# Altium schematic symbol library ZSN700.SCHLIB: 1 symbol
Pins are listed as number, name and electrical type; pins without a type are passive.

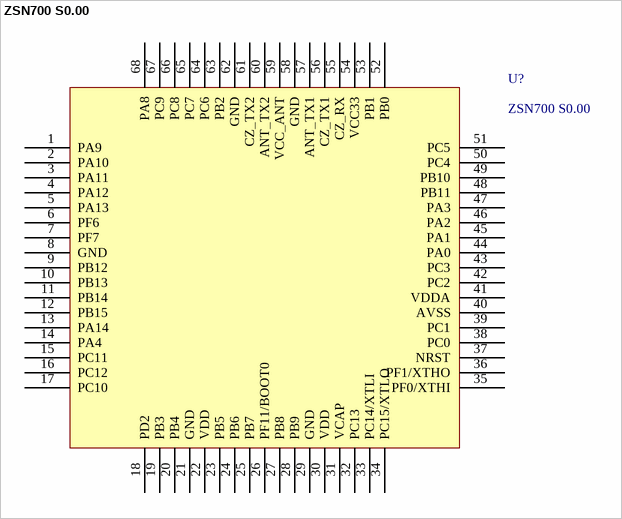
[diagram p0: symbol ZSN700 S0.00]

## ZSN700 S0.00
designator U?
物料代码: 78.59.00018; 名称: 集成电路; 厂商: ZHIYUAN; 贴片和直插: SMT; PCB备注: 200310hcj; 器件优选方案: 待导入物料
footprint ZSN700 S0.00
pins: 1 PA9, 2 PA10, 3 PA11, 4 PA12, 5 PA13, 6 PF6, 7 PF7, 8 GND, 9 PB12, 10 PB13, 11 PB14, 12 PB15, 13 PA14, 14 PA4, 15 PC11, 16 PC12, 17 PC10, 18 PD2, 19 PB3, 20 PB4, 21 GND, 22 VDD, 23 PB5, 24 PB6, 25 PB7, 26 PF11/BOOT0, 27 PB8, 28 PB9, 29 GND, 30 VDD, 31 VCAP, 32 PC13, 33 PC14/XTLI, 34 PC15/XTLO, 35 PF0/XTHI, 36 PF1/XTHO, 37 NRST, 38 PC0, 39 PC1, 40 AVSS, 41 VDDA, 42 PC2, 43 PC3, 44 PA0, 45 PA1, 46 PA2, 47 PA3, 48 PB11, 49 PB10, 50 PC4, 51 PC5, 52 PB0, 53 PB1, 54 VCC33, 55 CZ_RX, 56 CZ_TX1, 57 ANT_TX1, 58 GND, 59 VCC_ANT, 60 ANT_TX2, 61 CZ_TX2, 62 GND, 63 PB2, 64 PC6, 65 PC7, 66 PC8, 67 PC9, 68 PA8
